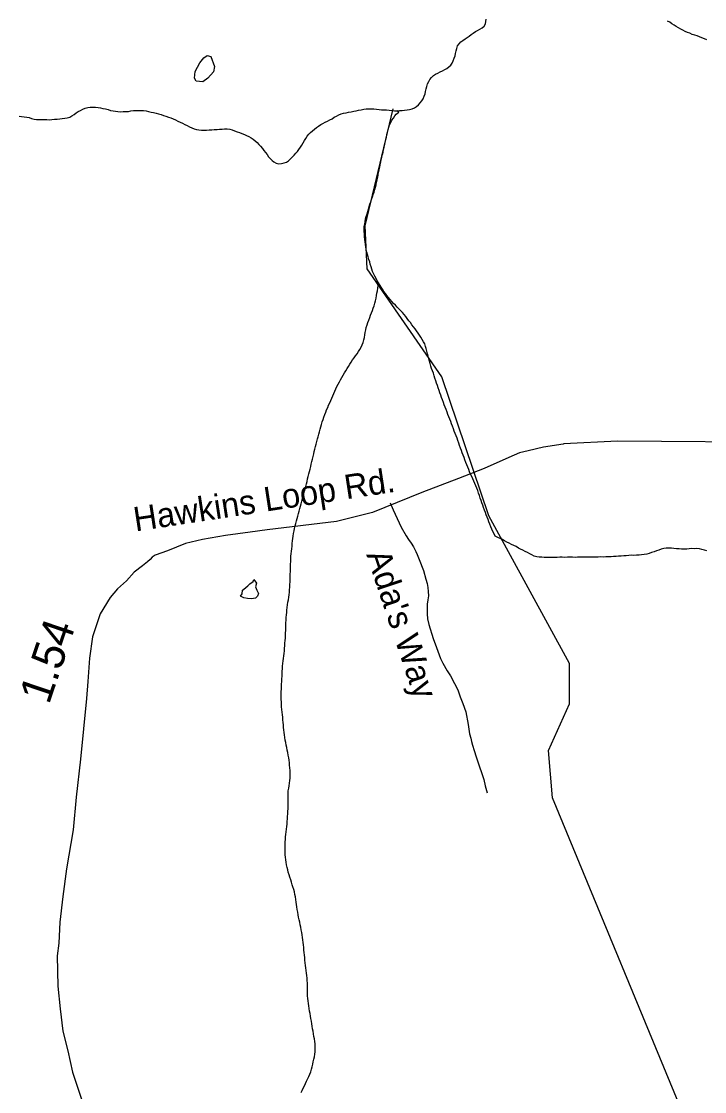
# Model space of a CAD drawing. Extents: x 1950930 to 2061844, y 904556 to 1017002.
# Drawn here: x 1978977 to 1981646, y 913941 to 918120 of the extents above; entities that cross this region are included whole.
import ezdxf

# ---------------------------------------------------------------- set-up
doc = ezdxf.new("R2010")
doc.units = 0
for name, color, linetype in [('Exist Hydrographic Creek Single Shore', 7, 'Continuous'), ('Exist Hydrographic Misc Water Feature', 7, 'Continuous'), ('Exist Road Non-System Type 51', 7, 'Continuous'), ('Exist Road Non-System Type 51 Label', 7, 'Continuous'), ('Exist Road Primary US Structure Standard Bridge CELL', 7, 'Continuous'), ('Exist Road Secondary Type 51 Attributed', 7, 'Continuous'), ('Exist Road Secondary Type 51 Label', 7, 'Continuous')]:
    doc.layers.add(name, color=color, linetype=linetype)

msp = doc.modelspace()

# ---------------------------------------------------------------- linework, layer by layer
at = {"layer": 'Exist Hydrographic Creek Single Shore'}
for points in [[(1980443.9, 917771.3), (1980453.7, 917771.8), (1980464.2, 917773), (1980474, 917773.5), (1980483.7, 917775.4), (1980493.7, 917776.7), (1980503.3, 917778.9), (1980512.6, 917782.8), (1980521.2, 917788.3), (1980528.2, 917795), (1980535.3, 917802.1), (1980541.7, 917809.9), (1980547, 917818.1), (1980551.1, 917828), (1980554, 917836.9), (1980556.4, 917846.8), (1980558.5, 917856.6), (1980561, 917866.3), (1980564.2, 917876), (1980568.3, 917885.1), (1980573.5, 917893.2), (1980579.4, 917901.2), (1980586.6, 917908.7), (1980594.8, 917913.9), (1980603.6, 917918.6), (1980612.8, 917923.3), (1980621.7, 917927.3), (1980630.9, 917932), (1980639.3, 917936.8), (1980647.5, 917942.4), (1980654.7, 917949.9), (1980660.4, 917957.9), (1980664.3, 917966.6), (1980668.2, 917976.7), (1980671.3, 917985.5), (1980673.7, 917995.2), (1980676.2, 918005.1), (1980678.2, 918014.9), (1980681.1, 918024.5), (1980687.3, 918032.5), (1980694.4, 918040), (1980702.2, 918045.8), (1980710.4, 918051.8), (1980718.2, 918057.5), (1980726.2, 918063.2), (1980734.6, 918069.6), (1980742.6, 918074.9), (1980751.2, 918080.4), (1980759.7, 918085.2), (1980768.7, 918090), (1980777.3, 918095.6), (1980784.9, 918101.3), (1980789.8, 918110.3), (1980791, 918119.9), (1980792.7, 918129.7)], [(1981654.5, 918048.6), (1981645.5, 918052.4), (1981635.8, 918056.7), (1981626.6, 918060.2), (1981617.2, 918063.7), (1981607.7, 918066.3), (1981598.1, 918069.7), (1981589.1, 918074.1), (1981579.5, 918077.5), (1981570.8, 918081.6), (1981561.8, 918085.8), (1981553.2, 918090.5), (1981544.2, 918095.5), (1981535.8, 918100.4), (1981526.8, 918105.8), (1981518.8, 918110.7), (1981509.9, 918116.9), (1981501.9, 918121.7)], [(1978967.9, 917749.8), (1978978, 917748.6), (1978988, 917747.9), (1978998.1, 917746.8), (1979007.5, 917744.9), (1979017.1, 917741.5), (1979026.8, 917738), (1979036.8, 917736.8), (1979046.4, 917736.6), (1979056.7, 917736.7), (1979066.5, 917737.3), (1979076.6, 917736.9), (1979086.8, 917736.5), (1979096.7, 917737.5), (1979107.1, 917738), (1979117, 917738.5), (1979127.2, 917739.4), (1979136.9, 917740.7), (1979146.7, 917742.1), (1979156.4, 917743.4), (1979165.8, 917746.5), (1979174.2, 917751.3), (1979182.8, 917756.8), (1979191.2, 917763.3), (1979199.4, 917769), (1979208, 917772.9), (1979217.7, 917777.5), (1979226.9, 917781.4), (1979236.5, 917783.6), (1979246.2, 917785), (1979256.2, 917786), (1979266.3, 917785.5), (1979276.7, 917784.4), (1979286.6, 917782.5), (1979296, 917780.6), (1979306.2, 917778.3), (1979315.7, 917775.7), (1979325.3, 917772.9), (1979335.2, 917771.1), (1979344.8, 917770), (1979354.6, 917768.1), (1979364.9, 917767.8), (1979374.7, 917767.9), (1979385, 917768.3), (1979395.2, 917768.8), (1979405.3, 917770.6), (1979414.9, 917771.9), (1979425.2, 917772.4), (1979435, 917772.9), (1979444.7, 917772.6), (1979454.7, 917771.9), (1979464.3, 917770.9), (1979474.2, 917768.9), (1979484, 917766.3), (1979493.9, 917764.3), (1979503.7, 917761.7), (1979513.3, 917759), (1979522.8, 917756.3), (1979532.8, 917752.7), (1979542.1, 917750.2), (1979551.3, 917746.7), (1979560.9, 917743.2), (1979570.6, 917739.7), (1979579.4, 917736.3), (1979588.6, 917731.3), (1979597.8, 917727.1), (1979606.2, 917722.5), (1979615.3, 917717.5), (1979624.3, 917713.3), (1979633.5, 917709.1), (1979642.5, 917704.9), (1979651.8, 917701.4), (1979660.8, 917698), (1979670.4, 917697), (1979680.9, 917695.7), (1979691.1, 917695.4), (1979701, 917695.9), (1979711.2, 917696.9), (1979721.1, 917697.4), (1979730.9, 917697.9), (1979741.4, 917698.7), (1979751.2, 917699.3), (1979761.1, 917699.8), (1979770.9, 917700.3), (1979781.1, 917700.4)], [(1979781.1, 917700.4), (1979791.2, 917699.3), (1979800.8, 917696.6), (1979810.1, 917693.2), (1979819.7, 917689.7), (1979829.3, 917686.2), (1979839, 917682.7), (1979848.2, 917679.2), (1979857.2, 917674.6), (1979866.2, 917670.4), (1979875.1, 917665.4), (1979883.3, 917660.6), (1979890.8, 917654.5), (1979898, 917647.8), (1979905.4, 917640.2), (1979911.8, 917632.7), (1979918.5, 917624.4), (1979924.3, 917616.2), (1979930.6, 917607.9), (1979937, 917600.4), (1979943.1, 917591.8), (1979950.1, 917584.2), (1979956.5, 917577.5), (1979963.6, 917571.6), (1979972.3, 917566.7), (1979982.1, 917564.7), (1979993.2, 917565.5), (1980003.4, 917567.6), (1980012.4, 917570.7), (1980020.4, 917576.4), (1980028.4, 917583.7), (1980036.2, 917591.1), (1980042.8, 917597.3), (1980049.6, 917605.2), (1980055.9, 917612.4), (1980061.5, 917620.5), (1980067.2, 917629.7), (1980072.3, 917637.5), (1980077.7, 917646.4), (1980083, 917655.3), (1980088.1, 917663.4), (1980093.6, 917671.5), (1980100.2, 917679.8), (1980106.6, 917687), (1980113.9, 917693.2), (1980121.7, 917699.7), (1980130.1, 917706.2), (1980138.3, 917711.8), (1980147, 917717.5), (1980155.4, 917722.2), (1980164.2, 917726.6), (1980173.4, 917730.9), (1980182.2, 917735.6), (1980191, 917740.3), (1980199.7, 917746), (1980208.1, 917750.4), (1980216.9, 917755.1), (1980226.1, 917759.4), (1980235.7, 917761.6), (1980245.6, 917763.7), (1980255.6, 917765.9), (1980265.7, 917767.5), (1980275.3, 917769.8), (1980285, 917771.1), (1980294.8, 917773.2), (1980304.4, 917775.5), (1980314.5, 917777.1), (1980324.5, 917778.5), (1980334.4, 917779), (1980344.4, 917778.7), (1980354.3, 917778.8), (1980364.3, 917777.8), (1980374.4, 917776.6), (1980384.4, 917775.5), (1980394, 917775.6), (1980404.1, 917774.5), (1980414.1, 917773.3), (1980424.2, 917772.2), (1980434.2, 917771.2), (1980443.9, 917771.3)], [(1981593.1, 913521.8), (1981593.1, 913781), (1981052, 915088.5), (1981036, 915272.7), (1981119, 915454.8), (1981119, 915612.3), (1980803, 916189.8), (1980619.9, 916731.9), (1980327.9, 917154.6), (1980319.9, 917322.2), (1980429, 917779.4)], [(1980223.9, 916721.1), (1980228.8, 916730.1), (1980233.9, 916738.3), (1980239.2, 916747.3), (1980244.6, 916755.4), (1980250.3, 916764.3), (1980255, 916772.5), (1980260.8, 916781.3), (1980265.9, 916789.5), (1980271.2, 916798.4), (1980276.8, 916806.4), (1980282.7, 916814.5), (1980288.4, 916822.5), (1980294.2, 916831.4), (1980299.3, 916839.5), (1980304.2, 916848.6), (1980308.5, 916857.3), (1980312.2, 916866.4), (1980315.1, 916876.1), (1980317.2, 916886), (1980318.8, 916895.8), (1980320.8, 916905.7), (1980322.5, 916915.2), (1980324.5, 916925), (1980327.6, 916935.1), (1980330.9, 916944.7), (1980334, 916953.6), (1980337.9, 916963.6), (1980341.3, 916972.4), (1980345.4, 916981.5), (1980348.7, 916991.2), (1980352, 917000), (1980355.3, 917010), (1980358.2, 917019.8), (1980360.6, 917029.5), (1980362.7, 917039.4), (1980364.9, 917049.2), (1980366, 917058.7), (1980368, 917068.6), (1980369.2, 917078.5), (1980370.5, 917088.5), (1980372.7, 917099.1)], [(1980828.3, 916109.8), (1980823.8, 916119), (1980819.5, 916128.2), (1980815.4, 916137.3), (1980811.5, 916146.5), (1980807.6, 916156.4), (1980803.9, 916165.4), (1980800.5, 916174.6), (1980796.8, 916183.6), (1980793.3, 916193.4), (1980789.8, 916202.5), (1980786.1, 916211.6), (1980782.6, 916221.4), (1980779.5, 916230.8), (1980776.5, 916239.9), (1980773, 916249.7), (1980769.7, 916258.7), (1980766.8, 916268.5), (1980763.1, 916278), (1980760.3, 916287.7), (1980756.2, 916296.9), (1980752.7, 916306), (1980748.6, 916315.1), (1980744.7, 916324.2), (1980740.6, 916333.4), (1980736.3, 916342.6), (1980732.2, 916351.7), (1980728.1, 916360.8), (1980724.6, 916370.3), (1980721.1, 916379.7), (1980717.6, 916388.8), (1980713.9, 916397.9), (1980710, 916407.8), (1980707, 916416.8), (1980702.9, 916425.9), (1980699.4, 916435.8), (1980696.3, 916444.8), (1980692.6, 916453.8), (1980689.3, 916464.1), (1980686, 916473.1), (1980682.8, 916483), (1980679.1, 916492.1), (1980675.6, 916501.1), (1980672.1, 916510.9), (1980668.4, 916520.1), (1980665.3, 916529.5), (1980661.4, 916538.9), (1980657.7, 916548.1), (1980654.3, 916557.5), (1980650.8, 916566.6), (1980647.3, 916576.5), (1980643.6, 916585.5), (1980640.1, 916594.6), (1980636.2, 916604.5), (1980632.9, 916613.5), (1980629.4, 916622.6), (1980625.8, 916631.6), (1980622.5, 916641.9), (1980618.8, 916651), (1980615.9, 916660.7), (1980611.8, 916669.9), (1980609.1, 916678.9), (1980605.7, 916688.7), (1980602.6, 916698.1), (1980599.5, 916707.9), (1980595.8, 916716.9), (1980592.7, 916726.8), (1980589.7, 916735.8), (1980586.6, 916745.9), (1980583.5, 916755), (1980580, 916764.8), (1980577.4, 916773.7), (1980574.3, 916784), (1980571.2, 916793), (1980568.5, 916802.7), (1980565.9, 916812.8), (1980563.8, 916822.5), (1980561.2, 916832.7), (1980558.9, 916842.3), (1980556.2, 916851.2), (1980552.8, 916860.7), (1980548.2, 916869.5), (1980542.9, 916878), (1980537.8, 916886.5), (1980532.5, 916895.4), (1980527.1, 916903.1), (1980521.2, 916911.3), (1980515.2, 916919.5), (1980509.1, 916927.8), (1980503.1, 916935.6), (1980496.8, 916943.9), (1980490.8, 916951.3), (1980484.7, 916959.5), (1980478.7, 916967.3), (1980472, 916975.7), (1980466, 916983.1), (1980459.3, 916990.6), (1980452.3, 916998.1), (1980444.9, 917004.9), (1980438.1, 917011.7)], [(1980010.4, 915761.8), (1980010.8, 915771.4), (1980011.8, 915782.3), (1980012, 915791.9), (1980012.4, 915802.1), (1980013.7, 915811.6), (1980014.5, 915821.2), (1980015.7, 915831.2), (1980017, 915842), (1980018.6, 915851.8), (1980020.2, 915861.7), (1980021.9, 915871.2), (1980023.5, 915881.1), (1980024.3, 915891.2), (1980025.2, 915900.8), (1980026, 915910.8), (1980026.4, 915921.3), (1980026.8, 915931), (1980027.2, 915941), (1980027.4, 915950.7), (1980027.4, 915960.9), (1980028, 915971.3), (1980028.2, 915981.1), (1980028.6, 915991.1), (1980028.6, 916000.9), (1980029.5, 916010.5), (1980029.9, 916020.6), (1980030.3, 916031.1), (1980031.5, 916041.1), (1980032.3, 916051), (1980033.2, 916060.6), (1980034.4, 916070.6), (1980034.8, 916081.2), (1980036.4, 916091), (1980038.1, 916100.9), (1980039.3, 916110.5), (1980040.5, 916120.4), (1980042.6, 916130.3), (1980044.2, 916140.1), (1980046.7, 916149.9), (1980049.1, 916159.7), (1980052, 916169.4), (1980054.5, 916178.3), (1980057.4, 916188.1), (1980059.4, 916197.9), (1980062.3, 916207.6), (1980064.7, 916217.8), (1980067.2, 916227.1), (1980070.1, 916236.1), (1980072.5, 916246.2), (1980075.4, 916256), (1980077.9, 916265.7), (1980080.3, 916275.4), (1980082.8, 916285.3), (1980085.6, 916294.2), (1980088.1, 916303.9), (1980090.6, 916313.7), (1980093, 916323.4), (1980095.5, 916333.7), (1980098, 916343.4), (1980100.6, 916353.2), (1980103.1, 916362.9), (1980105.3, 916371.9), (1980107.4, 916381.8), (1980109.8, 916391.5), (1980112.3, 916401.2), (1980114.4, 916411.1), (1980116.8, 916420.9), (1980119.1, 916430.8), (1980121.5, 916440.5), (1980124, 916450.2), (1980126, 916460.1), (1980128.9, 916469.8), (1980131, 916479.7), (1980133.4, 916489.4), (1980136.1, 916498.3), (1980138.8, 916508.1), (1980141.2, 916517.8), (1980144.1, 916527.6), (1980146.8, 916536.5), (1980149.8, 916546.6), (1980152.7, 916556.3), (1980156, 916565.9), (1980159.1, 916574.8), (1980163, 916584.8), (1980166, 916593.6), (1980169.7, 916602.8), (1980173.8, 916612.3), (1980177.5, 916621.5), (1980181.6, 916630.2), (1980185.7, 916640.1), (1980189.8, 916648.8), (1980193.5, 916658.1), (1980197.6, 916667.5), (1980201.7, 916676.6), (1980205.6, 916685.4), (1980210.1, 916694.5), (1980214.6, 916703.5), (1980219.5, 916712.5), (1980223.9, 916721.1)], [(1981380.1, 916035.2), (1981370.3, 916034.7), (1981360.3, 916035), (1981349.8, 916034.2), (1981340.4, 916033.6), (1981330.5, 916033.1), (1981320.1, 916031.7), (1981310.2, 916031.2), (1981300.4, 916030.3), (1981290.5, 916029.8), (1981280.7, 916029.3), (1981270.4, 916029.2), (1981260.6, 916028.7), (1981250.8, 916028.1), (1981240.5, 916028.5), (1981230.7, 916027.5), (1981220.4, 916027.8), (1981210.8, 916028.1), (1981200.5, 916027.6), (1981190.3, 916027.5), (1981180.4, 916027.8), (1981170.2, 916027.3), (1981160.5, 916027.6), (1981150.3, 916027.9), (1981140.4, 916027), (1981130.2, 916027.3), (1981120.5, 916027.6), (1981110.5, 916027.9), (1981100, 916027.1), (1981090.4, 916027.3), (1981080.6, 916027.6), (1981070.3, 916027.1), (1981060.1, 916027), (1981050.6, 916026.5), (1981040.6, 916026.8), (1981030.3, 916027.1), (1981020.1, 916027), (1981010.4, 916027.3), (1981000.4, 916027.6), (1980990.7, 916029.5), (1980981.1, 916032.1), (1980971.7, 916036.5), (1980962.9, 916040.7), (1980954, 916046), (1980945.4, 916050.2), (1980936.4, 916055.2), (1980927.4, 916059.4), (1980918.8, 916063.6), (1980910, 916069), (1980900.7, 916073.3), (1980891.7, 916077.5), (1980882.7, 916082.5), (1980874.1, 916086.6), (1980865.1, 916091.2), (1980856.2, 916096.2), (1980847.6, 916100.4), (1980838.4, 916104.6), (1980828.3, 916109.8)], [(1981655.1, 916052.7), (1981645.3, 916055.4), (1981636, 916058), (1981625.8, 916060.7), (1981616.2, 916061.8), (1981606.3, 916060.9), (1981596.1, 916061.3), (1981586.6, 916059.8), (1981576.4, 916059.4), (1981566.3, 916058.5), (1981556.3, 916058.8), (1981546.6, 916059.8), (1981536.6, 916061), (1981526.5, 916062.1), (1981516.5, 916062.8), (1981506.9, 916063), (1981496.4, 916062.6), (1981487, 916061.2), (1981476.7, 916058.7), (1981467.3, 916055.6), (1981458.3, 916052.5), (1981448.6, 916048.8), (1981439.2, 916045.7), (1981430, 916042.7), (1981420.1, 916040.1), (1981410.1, 916038.8), (1981400, 916037.5), (1981390.2, 916036.1), (1981380.1, 916035.2)], [(1980025.8, 914777.7), (1980022.7, 914786.8), (1980020, 914796.9), (1980017.8, 914806.5), (1980015.7, 914816.2), (1980013.5, 914826.2), (1980012.2, 914836.2), (1980010, 914846.3), (1980009.2, 914856.2), (1980007.7, 914865.7), (1980007.3, 914875.5), (1980007.3, 914885.7), (1980007.1, 914895.4), (1980007.9, 914905.1), (1980008.1, 914915.9), (1980009.2, 914925.6), (1980009.6, 914935.6), (1980010.8, 914945.2), (1980011.6, 914955.2), (1980012.4, 914965.7), (1980013.7, 914975.6), (1980014.9, 914985.6), (1980015.7, 914995.2), (1980016.5, 915005.2), (1980017.4, 915014.8), (1980018.2, 915025.6), (1980018.6, 915035.3), (1980019, 915045.4), (1980019, 915055.2), (1980018.8, 915064.9), (1980018.8, 915075.5), (1980018.8, 915085.6), (1980018.8, 915095.4), (1980019.6, 915105.4), (1980020, 915115), (1980021.7, 915125.7), (1980022.9, 915135.3), (1980024.1, 915145.3), (1980025.4, 915155.2), (1980026.6, 915164.8), (1980027, 915174.8), (1980026.8, 915184.7), (1980027, 915195.1), (1980026.4, 915205), (1980025.2, 915214.9), (1980024.7, 915224.8), (1980022.9, 915234.7), (1980022.1, 915244.6), (1980019.8, 915254.7), (1980018, 915264.3), (1980015.9, 915274.4), (1980013.7, 915284), (1980012, 915294.1), (1980009.8, 915304.1), (1980008.3, 915312.8), (1980006.5, 915322.9), (1980005.5, 915333.5), (1980004, 915343.5), (1980003, 915353), (1980001.8, 915363), (1980001.4, 915373.1), (1979999.9, 915382.7), (1979999.1, 915392.6), (1979998.1, 915402.4), (1979996.9, 915412.4), (1979996, 915423), (1979994.8, 915433), (1979993.8, 915442.9), (1979993, 915452.8), (1979993, 915462.5), (1979992.3, 915472.4), (1979992.3, 915482.5), (1979992.3, 915493.1), (1979992.3, 915502.8), (1979993.2, 915512.7), (1979993.2, 915522.5), (1979993.8, 915532.1), (1979994.2, 915542.3), (1979994.8, 915552.7), (1979995.6, 915562.8), (1979995.8, 915572.4), (1979996.2, 915582.2), (1979997.1, 915592.1), (1979997.9, 915602.6), (1979998.7, 915612.6), (1979999.9, 915622.6), (1980001.2, 915632.1), (1980002, 915642.1), (1980003.2, 915652.1), (1980004.9, 915661.6), (1980005.7, 915672.4), (1980006.1, 915682.1), (1980006.9, 915692.1), (1980008.1, 915702), (1980008.5, 915711.8), (1980008.8, 915721.4), (1980009.4, 915732.4), (1980009.8, 915742), (1980010.4, 915751.6), (1980010.4, 915761.8)], [(1980069.7, 913936.7), (1980074, 913945.3), (1980078.5, 913954.5), (1980082.6, 913963.6), (1980087.5, 913972.1), (1980091.6, 913981.2), (1980095.7, 913991.2), (1980100.2, 913999.9), (1980103.7, 914009), (1980107.4, 914017.8), (1980110.3, 914027.5), (1980113.1, 914037.2), (1980115.8, 914047.3), (1980117.6, 914056.8), (1980119.7, 914066.6), (1980121.7, 914076.5), (1980123.4, 914086.4), (1980124.6, 914096.4), (1980125, 914106), (1980125.2, 914117), (1980124.6, 914126.8), (1980123.8, 914136.6), (1980121.9, 914146.3), (1980120.3, 914156.2), (1980118.5, 914166.3), (1980116.8, 914175.9), (1980115, 914185.9), (1980113.7, 914195.8), (1980111.9, 914205.8), (1980110, 914215.4), (1980108.4, 914225.4), (1980106.8, 914235.5), (1980104.9, 914245), (1980103.1, 914255.1), (1980101.4, 914265), (1980100, 914275), (1980098.8, 914284.5), (1980096.9, 914294.5), (1980096.1, 914304.4), (1980095.1, 914314.3), (1980094.7, 914324.1), (1980094.3, 914333.9), (1980094.3, 914344.1), (1980094.3, 914354.6), (1980094.3, 914364.4), (1980093.6, 914374.2), (1980093.2, 914383.9), (1980092.2, 914393.9), (1980091.4, 914403.7), (1980090.2, 914413.7), (1980088.7, 914423.6), (1980087.5, 914433.6), (1980086.1, 914443.5), (1980084.8, 914454.3), (1980084, 914463.7), (1980083, 914473.5), (1980082.2, 914483.5), (1980081.1, 914493.3), (1980080.3, 914503.2), (1980079.5, 914513.1), (1980078.1, 914523.1), (1980077.2, 914532.9), (1980075.4, 914543), (1980074.2, 914552.9), (1980072.3, 914562.4), (1980070.3, 914572.6), (1980068.4, 914582.1), (1980066.2, 914592.2), (1980064.5, 914602.2), (1980062.3, 914611.9), (1980060.2, 914621.9), (1980058.4, 914631.5), (1980056.7, 914641.6), (1980054.5, 914651.6), (1980053.2, 914661.6), (1980051.8, 914671.5), (1980051, 914681), (1980049.1, 914691), (1980047.9, 914700.9), (1980046.1, 914710.9), (1980043.8, 914720.6), (1980041.6, 914729.9), (1980038.1, 914739.7), (1980035.4, 914748.7), (1980031.9, 914758.6), (1980029.3, 914767.5), (1980025.8, 914777.7)]]:
    msp.add_lwpolyline(points, dxfattribs=at)
at = {"layer": 'Exist Hydrographic Misc Water Feature'}
for points in [[(1979660, 917886.4), (1979653.8, 917898.3), (1979655.7, 917924.5), (1979673.7, 917958.2), (1979689.3, 917978.6), (1979703, 917986.6), (1979717.4, 917982.8), (1979731.7, 917944.9), (1979727.6, 917922.8), (1979705.7, 917898.5), (1979686, 917884.5), (1979660, 917886.4)], [(1980372.7, 917099.1), (1980367.2, 917107.2), (1980362.9, 917116.5), (1980358, 917125.7), (1980353.9, 917133.6), (1980349.5, 917143.6), (1980346.5, 917153), (1980343.2, 917162), (1980340.3, 917171.8), (1980338.1, 917181.9), (1980335, 917190.9), (1980332.3, 917200.6), (1980329.2, 917210.4), (1980326.6, 917219.7), (1980323.9, 917229.4), (1980322.7, 917239.4), (1980321.3, 917249.3), (1980320, 917259.3), (1980319, 917269.2), (1980318.2, 917279.1), (1980317.2, 917288.9), (1980316.9, 917299.6), (1980316.3, 917309.3), (1980316.7, 917319.1), (1980318.4, 917328.9), (1980320, 917338.8), (1980322.1, 917348.7), (1980324.5, 917358.4), (1980327.4, 917368.2), (1980330.3, 917377.8), (1980333.1, 917386.7), (1980335.6, 917397), (1980338.9, 917406.6), (1980342.4, 917416.2), (1980345.4, 917425.1), (1980348.9, 917435.1), (1980352, 917443.9), (1980355.3, 917453.6), (1980358.2, 917463.3), (1980360.6, 917473), (1980363.1, 917482.1), (1980365.1, 917492.3), (1980367.2, 917502.1), (1980369.2, 917511.6), (1980371.3, 917521.3), (1980372.9, 917531.3), (1980375, 917541.1), (1980377, 917551), (1980379.1, 917560.8), (1980381.1, 917570.7), (1980383.2, 917580.4), (1980385.2, 917590.2), (1980387.9, 917600.1), (1980389.9, 917609.9), (1980392.4, 917619.7), (1980394.5, 917629.5), (1980396.5, 917639.3), (1980399, 917649.1), (1980401, 917658.5), (1980403.1, 917668.8), (1980405.5, 917678.1), (1980407.6, 917688.4), (1980409.6, 917697.8), (1980412.1, 917707.5), (1980415.4, 917716.8), (1980419.9, 917725.9), (1980425, 917734.4), (1980430.8, 917742.5), (1980435.5, 917751.4), (1980441.8, 917758.6), (1980452.1, 917766), (1980443.9, 917771.3)], [(1980438.1, 917011.7), (1980431.2, 917018.8), (1980424.4, 917026.3), (1980417.4, 917033.8), (1980411.3, 917041.7), (1980404.7, 917049.2), (1980399.4, 917057.3), (1980393, 917065.6), (1980387.7, 917074.1), (1980382.2, 917082.2), (1980372.7, 917099.1)], [(1979885.1, 915940), (1979895.4, 915925.7), (1979891.9, 915911.7), (1979897.4, 915899.5), (1979903.8, 915885.9), (1979899.9, 915875.6), (1979891.7, 915867.5), (1979876.1, 915865.4), (1979859.9, 915865.8), (1979845.7, 915869.2), (1979833.4, 915875.2), (1979839.4, 915885.2), (1979841.6, 915899.1), (1979845.7, 915902.9), (1979861.5, 915915.9), (1979869.5, 915923.6), (1979883.1, 915933.3), (1979885.1, 915940)]]:
    msp.add_lwpolyline(points, dxfattribs=at)
at = {"layer": 'Exist Road Non-System Type 51'}
msp.add_lwpolyline([(1980418.5, 916240.6), (1980429.6, 916212.8), (1980461.4, 916144.4), (1980479.9, 916111.1), (1980490, 916096.7), (1980499.5, 916082.6), (1980508.5, 916067.8), (1980518.6, 916049.7), (1980523.8, 916037.8), (1980531.2, 916019.1), (1980547.5, 915975.2), (1980557.2, 915942.3), (1980561.9, 915925.6), (1980564.8, 915908.8), (1980566.2, 915893.6), (1980567.1, 915877.4), (1980565, 915860.9), (1980563, 915844.8), (1980562.5, 915825.8), (1980562.5, 915807), (1980564.1, 915787.6), (1980569.1, 915765.1), (1980586.1, 915709.8), (1980598.8, 915674.6), (1980615, 915631.8), (1980623.9, 915613.4), (1980640.4, 915584.2), (1980653.9, 915564.6), (1980669.2, 915534.9), (1980681.8, 915509.9), (1980691.5, 915482.9), (1980701.9, 915455.8), (1980713, 915423.8), (1980722.8, 915373.8), (1980728.2, 915338.4), (1980732.5, 915321.3), (1980735.6, 915308.5), (1980739.5, 915293.8), (1980746.2, 915272.5), (1980754.5, 915247.4), (1980760.6, 915228.8), (1980767.4, 915208.7), (1980774.6, 915187.3), (1980781.4, 915166.8), (1980783.2, 915159.5), (1980789.6, 915134.4), (1980796.8, 915107.3)], dxfattribs=at)
at = {"layer": 'Exist Road Secondary Type 51 Attributed'}
msp.add_lwpolyline([(1981991.7, 916475.2), (1981306.6, 916481.4), (1981096.7, 916471.1), (1981093.8, 916469.4), (1981016.4, 916457.2), (1980957.5, 916443.2), (1980923.4, 916434.8), (1980881.4, 916416.8), (1980785.5, 916374.5), (1980684.2, 916334.5), (1980541.1, 916280.2), (1980349.1, 916201.9), (1980208.3, 916167.3), (1979937.6, 916134.3), (1979871.6, 916125.2), (1979774.4, 916113), (1979684.8, 916097.1), (1979618.8, 916081.1), (1979548.6, 916052.6), (1979499.2, 916035.9), (1979488.6, 916028.3), (1979480.2, 916019.2), (1979470.4, 916010.1), (1979450.6, 915994.1), (1979417.6, 915968.7), (1979387.2, 915935.2), (1979352.3, 915904.8), (1979323.5, 915869.9), (1979285.5, 915806.1), (1979255.1, 915716.4), (1979243, 915632.8), (1979236.5, 915542), (1979232, 915475.2), (1979208.7, 915238.7), (1979191, 915090.6), (1979179.1, 914962.5), (1979153.4, 914810), (1979139.5, 914702.6), (1979127.6, 914602.5), (1979123.8, 914520.5), (1979117, 914471.1), (1979120, 914352.5), (1979128.7, 914263.3), (1979139.4, 914176.7), (1979158, 914099.5), (1979176.9, 914016.7), (1979213, 913906.9)], dxfattribs=at)

# ---------------------------------------------------------------- texts
at = {"layer": 'Exist Road Non-System Type 51 Label'}
msp.add_text("Ada's Way", height=95, rotation=288.4609, dxfattribs=at).set_placement((1980323.9, 916038.5))
at = {"layer": 'Exist Road Primary US Structure Standard Bridge CELL'}
msp.add_text('1.54', height=125, rotation=71.2894, dxfattribs=at).set_placement((1979084.7, 915449.2))
at = {"layer": 'Exist Road Secondary Type 51 Label'}
msp.add_text('Hawkins Loop Rd.', height=95, rotation=8.6928, dxfattribs=at).set_placement((1979422.7, 916127.9))

doc.saveas('drawing.dxf')
